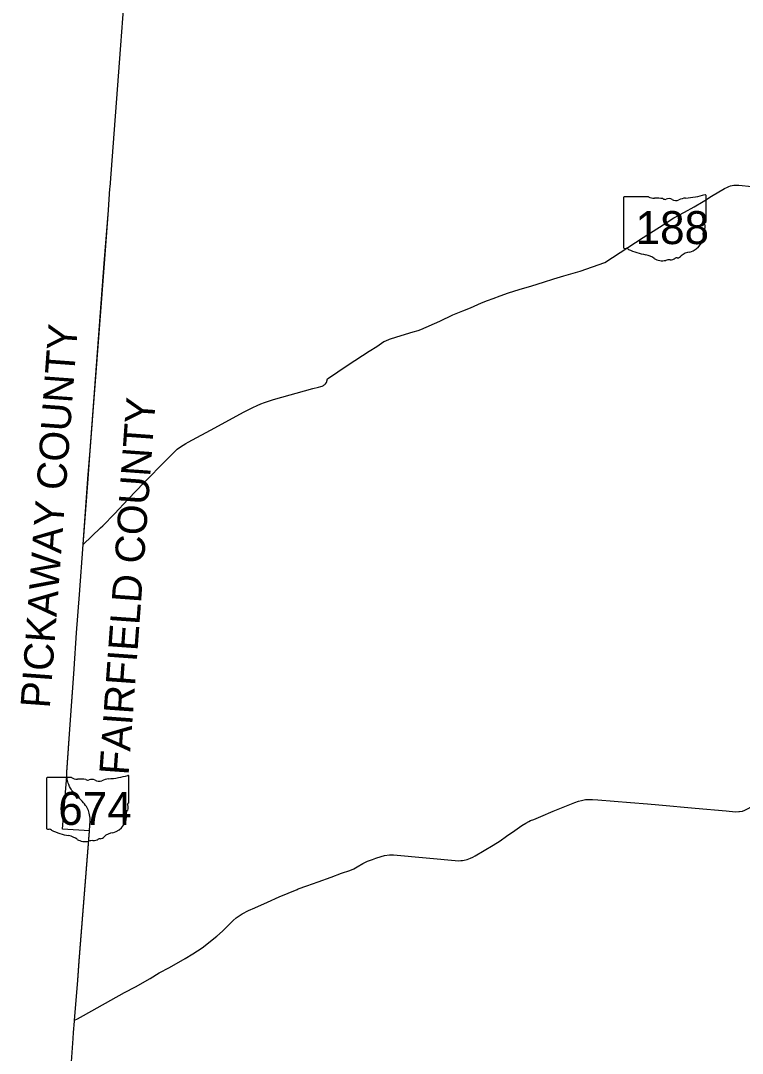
# Model space of a CAD drawing. Extents: x 1801177 to 2073177, y 551183 to 727183.
# Drawn here: x 1872004 to 1896545, y 593373 to 628489 of the extents above; entities that cross this region are included whole.
import ezdxf

# ---------------------------------------------------------------- set-up
doc = ezdxf.new("R2010")
doc.units = 0
for name, color, linetype in [('GM_X_County', 7, 'Continuous'), ('GM_X_County_Text', 7, 'Continuous'), ('GM_X_State_Location', 7, 'Continuous'), ('GM_X_State_Route', 7, 'Continuous'), ('GM_X_State_Shield', 7, 'Continuous'), ('GM_X_US_Route', 7, 'Continuous')]:
    doc.layers.add(name, color=color, linetype=linetype)

msp = doc.modelspace()

# ---------------------------------------------------------------- linework, layer by layer
at = {"layer": 'GM_X_County'}
msp.add_lwpolyline([(1873731, 593080), (1873788, 593881), (1873803, 594082), (1873831, 594466), (1873836, 594500), (1873943, 595858), (1873992, 596515), (1874345, 600935), (1873423, 600998), (1873572, 602800), (1873571, 602865), (1873573, 602930), (1873656, 604075), (1873745, 605346), (1873796, 606118), (1873820, 606446), (1873899, 607672), (1874001, 608980), (1874127, 610674), (1874293, 612908), (1874365, 613867), (1874849, 620230), (1874986, 622043), (1875040, 622781), (1875043, 622828), (1875413, 627659), (1875576, 629935)], dxfattribs=at)
at = {"layer": 'GM_X_State_Route'}
for points in [[(1875414, 627656), (1875577, 629933), (1875803, 632662), (1875883, 633996), (1876079, 636557), (1876124, 637211), (1876148, 637489), (1876186, 637930), (1876198, 638099), (1876584, 643285), (1876603, 643550)], [(1874128, 610671), (1874294, 612905), (1874367, 613864), (1874850, 620228), (1874987, 622040), (1875041, 622778), (1875045, 622825), (1875414, 627656)], [(1895207, 622342), (1895265, 622377), (1895500, 622519), (1895941, 622776), (1896042, 622830), (1896089, 622852), (1896141, 622870), (1896196, 622888), (1896253, 622900), (1896427, 622896), (1896871, 622847)], [(1893848, 621549), (1894211, 621779), (1894572, 621975), (1894904, 622155), (1895207, 622342)], [(1882442, 616310), (1883141, 616785), (1883854, 617251), (1884111, 617414), (1884357, 617577), (1884420, 617606), (1884549, 617659), (1884790, 617740), (1885356, 617913), (1885522, 617957), (1885612, 617987), (1886259, 618275), (1886705, 618482), (1887040, 618621), (1887301, 618727), (1887676, 618890), (1887874, 618971), (1888072, 619044), (1888304, 619137), (1888598, 619233), (1888960, 619345), (1889390, 619477), (1889788, 619600), (1890135, 619712), (1890470, 619809), (1891032, 619976), (1891866, 620263), (1893171, 621120), (1893848, 621549)], [(1882374, 616142), (1882400, 616183), (1882442, 616310)], [(1874128, 610671), (1874719, 611242), (1874797, 611316), (1875191, 611717), (1875661, 612215), (1876196, 612772), (1876949, 613549), (1877329, 613913), (1877436, 613993), (1877615, 614109), (1877697, 614154), (1877847, 614240), (1878459, 614569), (1879607, 615182), (1879896, 615336), (1880043, 615404), (1880171, 615462), (1880299, 615507), (1880598, 615603), (1881940, 615984), (1882129, 616028), (1882207, 616049), (1882254, 616065), (1882298, 616084), (1882326, 616100), (1882352, 616120), (1882374, 616142)], [(1873573, 602797), (1873572, 602862), (1873574, 602928), (1873657, 604072), (1873746, 605343), (1873797, 606115), (1873821, 606444), (1873901, 607669), (1874002, 608977), (1874128, 610671)], [(1874346, 600932), (1874358, 601144), (1874364, 601242), (1874364, 601308), (1874362, 601374), (1874357, 601423), (1874347, 601489), (1874337, 601537), (1874324, 601585), (1874307, 601632), (1874287, 601677), (1874265, 601721), (1874240, 601764), (1874212, 601805), (1874173, 601858), (1874141, 601896), (1874097, 601944), (1874017, 602027), (1873833, 602214), (1873778, 602274), (1873747, 602312), (1873719, 602352), (1873694, 602394), (1873664, 602452), (1873637, 602512), (1873620, 602558), (1873606, 602604), (1873594, 602652), (1873584, 602700), (1873573, 602797)], [(1873837, 594497), (1873944, 595855), (1873994, 596512), (1874346, 600932)]]:
    msp.add_lwpolyline(points, dxfattribs=at)
at = {"layer": 'GM_X_State_Shield'}
for p, q in [((1892508, 622472), (1892508, 620771)), ((1893356, 622502), (1892536, 622502)), ((1895310, 621654), (1895310, 622544)), ((1895309, 621654), (1895310, 621654)), ((1872885, 602722), (1872885, 601021)), ((1873734, 602751), (1872913, 602751)), ((1875687, 601903), (1875687, 602793)), ((1875687, 601904), (1875687, 601903))]:
    msp.add_line(p, q, dxfattribs=at)
for centre, major_axis, start_param, end_param in [((1892540, 622476), (32.5, 0), 1.712693, 3.28349), ((1893551, 622699), (315, 0), 4.042523, 4.731795), ((1893656, 621547), (1130, 0), 1.404758, 1.657858), ((1893912, 622485), (90.8, 0), 3.836095, 5.185415), ((1894046, 622288), (189, 0), 0.950623, 2.079405), ((1894289, 622558), (227, 0), 4.081561, 5.145723), ((1894691, 621982), (598, 0), 1.699011, 2.107814), ((1894312, 624821), (2971, 0), 4.814394, 5.042369), ((1895279, 622548), (31.2, 0), 6.141152, 7.989035), ((1895303, 621589), (48.3, 0), 1.883978, 3.671073), ((1894995, 621476), (290, 0), 5.934695, 6.695948), ((1895276, 621650), (33.4, 0), 5.05454, 6.418171), ((1894478, 621168), (743, 0), 5.101752, 6.440018), ((1895421, 621282), (211, 0), 2.387724, 3.262537), ((1892540, 620768), (32.7, 0), 3.00124, 4.508301), ((1892545, 620942), (250, 0), 4.665946, 4.897461), ((1892596, 620673), (90.1, 0), 0.519207, 1.627899), ((1893734, 622202), (2146, 0), 4.195997, 4.488961), ((1893094, 620007), (671, 0), 0.823519, 1.323587), ((1894276, 620606), (240, 0), 4.937069, 5.64225), ((1894791, 620294), (407, 0), 1.647645, 2.488434), ((1893820, 620665), (426, 0), 4.026481, 4.996735), ((1894067, 620076), (350, 0), 1.495662, 1.94098), ((1894098, 620537), (227, 0), 4.691044, 5.507374), ((1894303, 620372), (63.9, 0), 1.147584, 2.315152), ((1872918, 602726), (32.5, 0), 1.712693, 3.28349), ((1873929, 602949), (315, 0), 4.042523, 4.731795), ((1874033, 601796), (1130, 0), 1.404758, 1.657858), ((1874290, 602734), (90.8, 0), 3.836095, 5.185415), ((1874423, 602538), (189, 0), 0.950623, 2.079405), ((1874667, 602807), (227, 0), 4.081561, 5.145723), ((1875068, 602232), (598, 0), 1.699011, 2.107814), ((1874689, 605071), (2971, 0), 4.814394, 5.042369), ((1875656, 602797), (31.2, 0), 6.141152, 7.989035), ((1875654, 601900), (33.4, 0), 5.05454, 6.418171), ((1875799, 601531), (211, 0), 2.387724, 3.262537), ((1875680, 601838), (48.3, 0), 1.883978, 3.671073), ((1875373, 601726), (290, 0), 5.934695, 6.695948), ((1874856, 601418), (743, 0), 5.101752, 6.440018), ((1872918, 601017), (32.7, 0), 3.00124, 4.508301), ((1872923, 601191), (250, 0), 4.665946, 4.897461), ((1872974, 600923), (90.1, 0), 0.519207, 1.627899), ((1874112, 602451), (2146, 0), 4.195997, 4.488961), ((1875169, 600543), (407, 0), 1.647645, 2.488434), ((1873472, 600257), (671, 0), 0.823519, 1.323587), ((1874198, 600914), (426, 0), 4.026481, 4.996735), ((1874444, 600326), (350, 0), 1.495662, 1.94098), ((1874475, 600787), (227, 0), 4.691044, 5.507374), ((1874680, 600622), (63.9, 0), 1.147584, 2.315152), ((1874653, 600856), (240, 0), 4.937069, 5.64225)]:
    msp.add_ellipse(centre, major_axis=major_axis, ratio=0.8, start_param=start_param, end_param=end_param, dxfattribs=at)
at = {"layer": 'GM_X_US_Route'}
for points in [[(1896428, 601596), (1896449, 601597), (1896546, 601613), (1896626, 601640), (1896744, 601695), (1896850, 601759), (1897038, 601879), (1897218, 601999), (1898145, 602639), (1898681, 603042), (1899544, 603636), (1900426, 604264), (1900674, 604443)], [(1887084, 599942), (1887186, 599967), (1887249, 599987), (1887295, 600005), (1887384, 600048), (1887455, 600088), (1888070, 600452), (1888307, 600600), (1888526, 600753), (1888811, 600946), (1889050, 601119), (1889183, 601199), (1889283, 601257), (1889341, 601287), (1889452, 601325), (1889693, 601426), (1890107, 601605), (1890846, 601899), (1890978, 601948), (1891078, 601976), (1891216, 602002), (1891322, 602008), (1891451, 602008), (1891629, 601991), (1892744, 601907), (1893314, 601859), (1893707, 601824), (1894942, 601715), (1895997, 601616), (1896310, 601586), (1896428, 601596)], [(1881407, 598947), (1881446, 598964), (1881731, 599069), (1882124, 599211), (1882563, 599369), (1882913, 599499), (1883194, 599592), (1883329, 599645), (1883444, 599711), (1883644, 599824), (1883800, 599903), (1883864, 599928), (1883936, 599957), (1883963, 599966)], [(1883963, 599966), (1884081, 600009), (1884262, 600071), (1884379, 600098), (1884549, 600118), (1884685, 600124), (1886900, 599923), (1886976, 599928), (1887025, 599933), (1887084, 599942)], [(1873837, 594497), (1873931, 594546), (1874143, 594662), (1875531, 595438), (1875908, 595636), (1876406, 595924), (1876716, 596106), (1877070, 596288), (1877593, 596603), (1877858, 596758), (1878172, 596964), (1878330, 597082), (1878518, 597236), (1878671, 597362), (1878862, 597527), (1879226, 597885), (1879330, 597977), (1879430, 598053), (1879541, 598122), (1879749, 598228), (1879971, 598326), (1880399, 598519), (1880795, 598690), (1881407, 598947)]]:
    msp.add_lwpolyline(points, dxfattribs=at)

# ---------------------------------------------------------------- texts
at = {"layer": 'GM_X_County_Text'}
for s, rotation, p in [('PICKAWAY COUNTY', 85.7997, (1872993, 605089)), ('FAIRFIELD COUNTY', 85.8545, (1875671, 602813))]:
    msp.add_text(s, height=1000, rotation=rotation, dxfattribs=at).set_placement(p)
at = {"layer": 'GM_X_State_Location'}
msp.add_text('674', height=1, rotation=0, dxfattribs=at).set_placement((1873767, 601735))
for s in ['s', 'r']:
    msp.add_text(s, height=1, dxfattribs=at).set_placement((1874120, 601807))
at = {"layer": 'GM_X_State_Shield'}
for s, p in [('188', (1892913, 620891)), ('674', (1873281, 601141))]:
    msp.add_text(s, height=1120.7, dxfattribs=at).set_placement(p)

doc.saveas('drawing.dxf')
